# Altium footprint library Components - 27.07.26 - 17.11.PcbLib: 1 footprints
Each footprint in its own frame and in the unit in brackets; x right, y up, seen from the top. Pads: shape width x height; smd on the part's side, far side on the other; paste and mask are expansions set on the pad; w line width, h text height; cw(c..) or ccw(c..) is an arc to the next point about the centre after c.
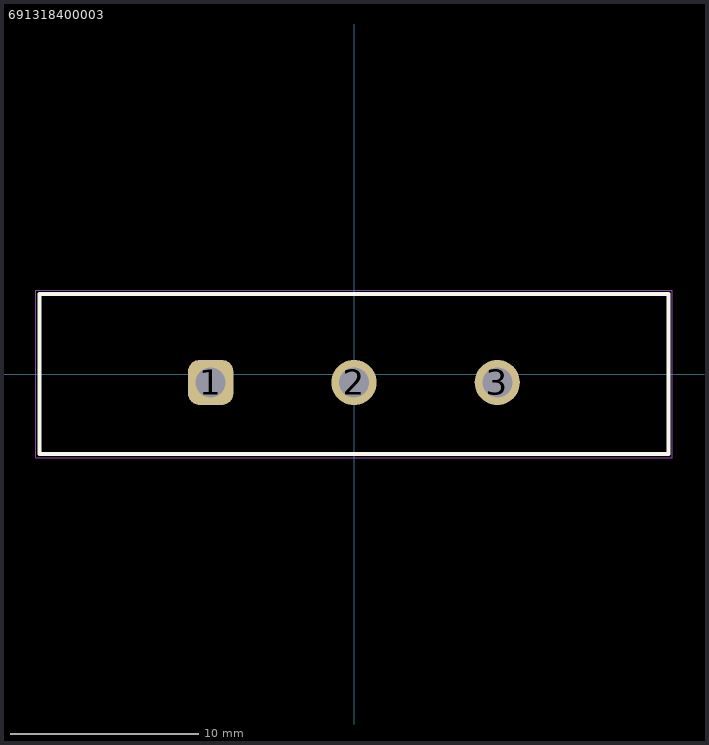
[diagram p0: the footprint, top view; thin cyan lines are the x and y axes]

## 691318400003 [mm] "7.62 mm - Closed Vertical PCB Header with Flanges - 3p"
height 12
pads (3):
  rrect50% 2.4x2.4 hole 1.6: 1(-7.62,-0.45)
  round 2.4 hole 1.6: 2(0,-0.45) 3(7.62,-0.45)
Top Overlay:
  lines w0.2: -16.72,-4.25 16.72,-4.25 16.72,4.25 -16.72,4.25 -16.72,-4.25
Top Assembly:
  lines w0.1: -16.72,-4.25 -16.72,4.25 16.72,4.25 16.72,-4.25 -16.72,-4.25
Top Designator:
  text ".Designator" at -3.647,-0.357 h1
Top 3D Body:
  lines w0.1: -16.72,-4.25 16.72,-4.25 16.72,4.25 -16.72,4.25 -16.72,-4.25
Top Courtyard:
  lines w0.05: -16.92,-4.45 -16.92,4.45 16.92,4.45 16.92,-4.45 -16.92,-4.45
Top Component Center:
  lines w0.1: -0.5,0 0.5,0 ; 0,-0.5 0,0.5
3D body "691318400003.stp": height 12.05, standoff -3.95, extent -16.72,-4.25 16.72,4.25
